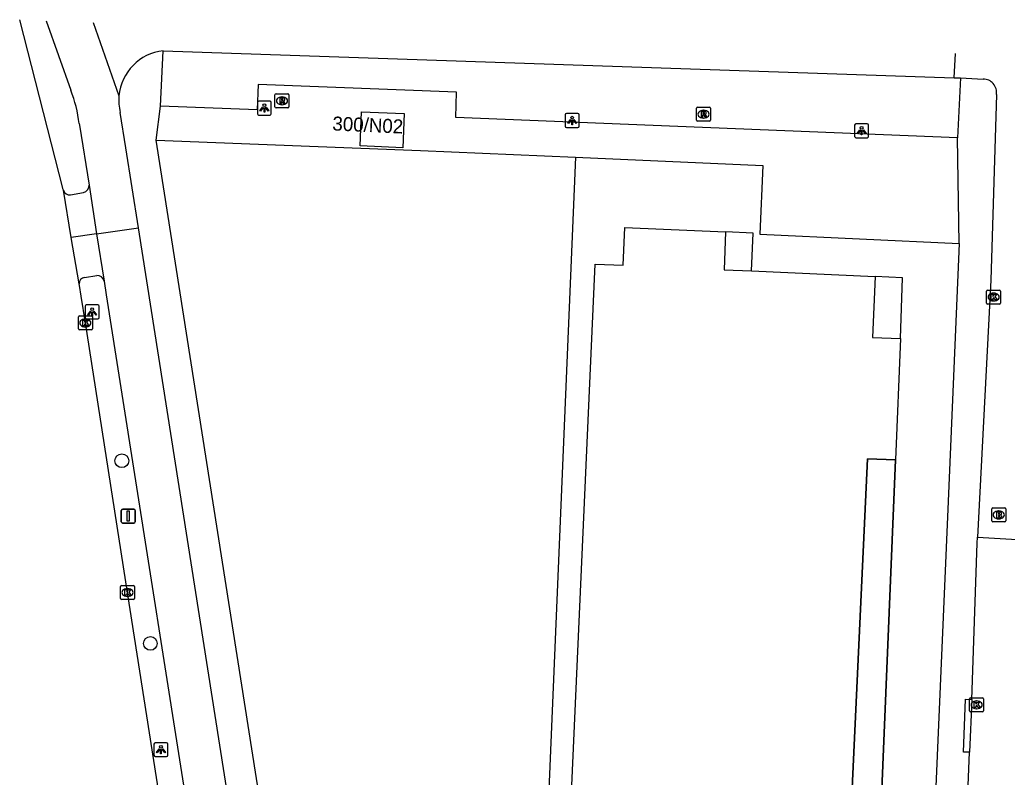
# Model space of a CAD drawing. Extents: x 160891 to 161384, y 386490 to 386907.
# Drawn here: x 160891.3 to 160961.8, y 386825.1 to 386879.2 of the extents above; entities that cross this region are included whole.
import ezdxf

# ---------------------------------------------------------------- set-up
doc = ezdxf.new("R2010")
doc.units = 0
for name, color, linetype in [('IMGEO_Boom', 7, 'Continuous'), ('IMGEO_Brandkraan', 7, 'Continuous'), ('IMGEO_Fietspad_gesloten', 7, 'Continuous'), ('IMGEO_Fietspad_open', 7, 'Continuous'), ('IMGEO_Kolk', 7, 'Continuous'), ('IMGEO_Lichtpunt', 7, 'Continuous'), ('IMGEO_Pand', 7, 'Continuous'), ('IMGEO_Pand_nummerreeks', 7, 'Continuous'), ('IMGEO_Pand_overbouw', 7, 'Continuous'), ('IMGEO_Rijbaan_lokaal_gesloten', 7, 'Continuous'), ('IMGEO_Rijbaan_lokaal_open', 7, 'Continuous'), ('IMGEO_Rioolput', 7, 'Continuous'), ('IMGEO_Verkeersbordpaal', 7, 'Continuous'), ('IMGEO_Voetpad_open', 7, 'Continuous')]:
    doc.layers.add(name, color=color, linetype=linetype)

msp = doc.modelspace()

# ---------------------------------------------------------------- linework, layer by layer
at = {"layer": 'IMGEO_Boom'}
for centre in [(160898.541, 386847.738), (160900.576, 386834.696)]:
    msp.add_circle(centre, 0.489, dxfattribs=at)
at = {"layer": 'IMGEO_Brandkraan'}
for p, q in [((160960.654, 386843.444), (160960.654, 386844.296)), ((160960.729, 386844.37), (160961.581, 386844.37)), ((160961.142, 386844.15), (160961.167, 386844.15)), ((160961.655, 386844.296), (160961.655, 386843.444)), ((160961.581, 386843.37), (160960.729, 386843.37)), ((160961.165, 386843.59), (160961.14, 386843.59))]:
    msp.add_line(p, q, dxfattribs=at)
for points in [[(160960.654, 386843.444), (160960.654, 386844.296)], [(160960.729, 386844.37), (160961.581, 386844.37)], [(160961.002, 386844.07), (160961.002, 386843.67), (160961.215, 386843.67)], [(160961.233, 386844.07), (160961.002, 386844.07)], [(160961.181, 386843.989), (160961.127, 386843.989), (160961.127, 386843.913)], [(160961.127, 386843.913), (160961.18, 386843.913)], [(160961.189, 386843.837), (160961.127, 386843.837), (160961.127, 386843.756)], [(160961.655, 386844.296), (160961.655, 386843.444)], [(160961.581, 386843.37), (160960.729, 386843.37)], [(160961.127, 386843.756), (160961.189, 386843.756)]]:
    msp.add_lwpolyline(points, dxfattribs=at)
for centre, radius, start, end in [((160960.731, 386844.294), 0.0765, 91.55205, 178.44795), ((160960.731, 386844.294), 0.0765, 91.55205, 178.44795), ((160961.182, 386843.951), 0.0379, 267.82845, 90.93552), ((160961.19, 386843.796), 0.0404, 269.87594, 90.50774), ((160961.237, 386843.925), 0.145, 59.4692, 91.53667), ((160961.262, 386843.972), 0.0922, 285.51372, 58.15012), ((160961.267, 386843.78), 0.105, 301.31148, 78.98903), ((160961.579, 386844.294), 0.0765, 1.55205, 88.44795), ((160961.579, 386844.294), 0.0765, 1.55205, 88.44795), ((160960.731, 386843.446), 0.0765, 181.55205, 268.44795), ((160960.731, 386843.446), 0.0765, 181.55205, 268.44795), ((160961.221, 386843.921), 0.251, 268.66757, 293.53466), ((160961.579, 386843.446), 0.0765, 271.55205, 358.44795), ((160961.579, 386843.446), 0.0765, 271.55205, 358.44795)]:
    msp.add_arc(centre, radius, start, end, dxfattribs=at)
for centre, major_axis, ratio, start_param, end_param in [((160961.141, 386843.87), (-0.387, 0.002), 0.722429, 4.712389, 7.853982), ((160961.166, 386843.87), (-0.39, 0.002), 0.717154, 1.570796, 4.712389)]:
    msp.add_ellipse(centre, major_axis=major_axis, ratio=ratio, start_param=start_param, end_param=end_param, dxfattribs=at)
at = {"layer": 'IMGEO_Fietspad_gesloten'}
for points in [[(160893.132, 386879.162), (160894.9, 386874.198)], [(160896.482, 386879.04), (160898.337, 386873.806)], [(160901.489, 386877.014), (160957.962, 386875.093)], [(160957.962, 386875.093), (160958.056, 386876.81)], [(160899.722, 386864.375), (160898.823, 386870.088), (160898.426, 386872.614)], [(160895.497, 386871.813), (160895.518, 386871.708), (160896.217, 386867.408)], [(160896.217, 386867.408), (160896.734, 386863.953)], [(160894.883, 386866.73), (160895.81, 386866.893)], [(160896.734, 386863.953), (160899.722, 386864.375)], [(160919.245, 386743.063), (160917.807, 386750), (160917.572, 386751.136), (160917.197, 386753.124), (160907.589, 386814.399), (160899.722, 386864.375)], [(160896.734, 386863.953), (160894.934, 386863.689)], [(160896.734, 386863.953), (160897.273, 386860.565)], [(160897.273, 386860.565), (160897.429, 386859.589), (160904.689, 386813.559), (160910.872, 386774.235), (160914.38, 386753.725), (160915.067, 386750), (160915.406, 386748.161), (160916.107, 386744.917), (160916.31, 386743.822)]]:
    msp.add_lwpolyline(points, dxfattribs=at)
for centre, radius, start, end in [((160901.888, 386873.47), 3.567, 96.42224, 174.58672), ((160885.253, 386870.516), 10.325, 7.21566, 20.89074), ((160901.872, 386873.471), 3.551, 174.5804, 193.95967), ((160894.793, 386867.155), 0.434, 193.70288, 281.96504), ((160895.601, 386867.477), 0.62, 289.71072, 353.65126)]:
    msp.add_arc(centre, radius, start, end, dxfattribs=at)
at = {"layer": 'IMGEO_Fietspad_open'}
for points in [[(160957.962, 386875.093), (160958.414, 386875.075)], [(160958.414, 386875.075), (160960.041, 386874.995)], [(160960.986, 386873.9), (160960.591, 386860.622), (160959.632, 386842.271)]]:
    msp.add_lwpolyline(points, dxfattribs=at)
msp.add_arc((160960.047, 386874.045), 0.95, 351.22726, 90.36203, dxfattribs=at)
at = {"layer": 'IMGEO_Kolk'}
for p, q in [((160960.287, 386859.002), (160960.287, 386859.854)), ((160960.362, 386859.928), (160961.214, 386859.928)), ((160960.775, 386859.708), (160960.8, 386859.708)), ((160961.288, 386859.854), (160961.288, 386859.002)), ((160961.214, 386858.928), (160960.362, 386858.928)), ((160960.798, 386859.148), (160960.773, 386859.148)), ((160895.436, 386857.151), (160895.436, 386858.003)), ((160895.511, 386858.077), (160896.363, 386858.077)), ((160896.437, 386858.003), (160896.437, 386857.151)), ((160895.947, 386857.297), (160895.922, 386857.297)), ((160895.924, 386857.857), (160895.949, 386857.857)), ((160896.363, 386857.077), (160895.511, 386857.077)), ((160898.443, 386837.906), (160898.443, 386838.758)), ((160898.518, 386838.832), (160899.37, 386838.832)), ((160898.931, 386838.612), (160898.956, 386838.612)), ((160899.444, 386838.758), (160899.444, 386837.906)), ((160899.37, 386837.832), (160898.518, 386837.832)), ((160898.954, 386838.052), (160898.929, 386838.052)), ((160959.074, 386829.883), (160959.074, 386830.735)), ((160959.149, 386830.809), (160960.001, 386830.809)), ((160959.562, 386830.589), (160959.587, 386830.589)), ((160960.075, 386830.735), (160960.075, 386829.883)), ((160960.001, 386829.809), (160959.149, 386829.809)), ((160959.585, 386830.029), (160959.56, 386830.029))]:
    msp.add_line(p, q, dxfattribs=at)
for points in [[(160960.287, 386859.002), (160960.287, 386859.854)], [(160960.362, 386859.928), (160961.214, 386859.928)], [(160960.608, 386859.628), (160960.731, 386859.628), (160960.731, 386859.477), (160960.861, 386859.628), (160961.025, 386859.628), (160960.879, 386859.477), (160961.032, 386859.228), (160960.88, 386859.228), (160960.795, 386859.392), (160960.731, 386859.325), (160960.731, 386859.228), (160960.608, 386859.228), (160960.608, 386859.628)], [(160961.288, 386859.854), (160961.288, 386859.002)], [(160961.214, 386858.928), (160960.362, 386858.928)], [(160895.436, 386857.151), (160895.436, 386858.003)], [(160895.511, 386858.077), (160896.363, 386858.077)], [(160896.437, 386858.003), (160896.437, 386857.151)], [(160895.757, 386857.777), (160895.88, 386857.777), (160895.88, 386857.626), (160896.01, 386857.777), (160896.174, 386857.777), (160896.028, 386857.626), (160896.181, 386857.377), (160896.029, 386857.377), (160895.944, 386857.541), (160895.88, 386857.474), (160895.88, 386857.377), (160895.757, 386857.377), (160895.757, 386857.777)], [(160896.363, 386857.077), (160895.511, 386857.077)], [(160898.443, 386837.906), (160898.443, 386838.758)], [(160898.518, 386838.832), (160899.37, 386838.832)], [(160898.764, 386838.532), (160898.887, 386838.532), (160898.887, 386838.381), (160899.017, 386838.532), (160899.181, 386838.532), (160899.035, 386838.381), (160899.188, 386838.132), (160899.036, 386838.132), (160898.951, 386838.296), (160898.887, 386838.229), (160898.887, 386838.132), (160898.764, 386838.132), (160898.764, 386838.532)], [(160899.444, 386838.758), (160899.444, 386837.906)], [(160899.37, 386837.832), (160898.518, 386837.832)], [(160959.074, 386829.883), (160959.074, 386830.735)], [(160959.149, 386830.809), (160960.001, 386830.809)], [(160959.395, 386830.509), (160959.518, 386830.509), (160959.518, 386830.358), (160959.648, 386830.509), (160959.812, 386830.509), (160959.666, 386830.358), (160959.819, 386830.109), (160959.667, 386830.109), (160959.582, 386830.273), (160959.518, 386830.206), (160959.518, 386830.109), (160959.395, 386830.109), (160959.395, 386830.509)], [(160960.075, 386830.735), (160960.075, 386829.883)], [(160960.001, 386829.809), (160959.149, 386829.809)]]:
    msp.add_lwpolyline(points, dxfattribs=at)
for centre, start, end in [((160960.364, 386859.852), 91.55205, 178.44795), ((160960.364, 386859.852), 91.55205, 178.44795), ((160961.212, 386859.852), 1.55205, 88.44795), ((160961.212, 386859.852), 1.55205, 88.44795), ((160960.364, 386859.004), 181.55205, 268.44795), ((160960.364, 386859.004), 181.55205, 268.44795), ((160961.212, 386859.004), 271.55205, 358.44795), ((160961.212, 386859.004), 271.55205, 358.44795), ((160895.513, 386858.001), 91.55205, 178.44795), ((160895.513, 386858.001), 91.55205, 178.44795), ((160896.361, 386858.001), 1.55205, 88.44795), ((160896.361, 386858.001), 1.55205, 88.44795), ((160895.513, 386857.153), 181.55205, 268.44795), ((160895.513, 386857.153), 181.55205, 268.44795), ((160896.361, 386857.153), 271.55205, 358.44795), ((160896.361, 386857.153), 271.55205, 358.44795), ((160898.52, 386838.756), 91.55205, 178.44795), ((160898.52, 386838.756), 91.55205, 178.44795), ((160899.368, 386838.756), 1.55205, 88.44795), ((160899.368, 386838.756), 1.55205, 88.44795), ((160898.52, 386837.908), 181.55205, 268.44795), ((160898.52, 386837.908), 181.55205, 268.44795), ((160899.368, 386837.908), 271.55205, 358.44795), ((160899.368, 386837.908), 271.55205, 358.44795), ((160959.151, 386830.733), 91.55205, 178.44795), ((160959.151, 386830.733), 91.55205, 178.44795), ((160959.999, 386830.733), 1.55205, 88.44795), ((160959.999, 386830.733), 1.55205, 88.44795), ((160959.151, 386829.885), 181.55205, 268.44795), ((160959.151, 386829.885), 181.55205, 268.44795), ((160959.999, 386829.885), 271.55205, 358.44795), ((160959.999, 386829.885), 271.55205, 358.44795)]:
    msp.add_arc(centre, 0.0765, start, end, dxfattribs=at)
for centre, major_axis, ratio, start_param, end_param in [((160960.774, 386859.428), (-0.387, 0.002), 0.722429, 4.712389, 7.853982), ((160960.799, 386859.428), (-0.39, 0.002), 0.717154, 1.570796, 4.712389), ((160895.923, 386857.577), (-0.387, 0.002), 0.722429, 4.712389, 7.853982), ((160895.948, 386857.577), (-0.39, 0.002), 0.717154, 1.570796, 4.712389), ((160898.93, 386838.332), (-0.387, 0.002), 0.722429, 4.712389, 7.853982), ((160898.955, 386838.332), (-0.39, 0.002), 0.717154, 1.570796, 4.712389), ((160959.561, 386830.309), (-0.387, 0.002), 0.722429, 4.712389, 7.853982), ((160959.586, 386830.309), (-0.39, 0.002), 0.717154, 1.570796, 4.712389)]:
    msp.add_ellipse(centre, major_axis=major_axis, ratio=ratio, start_param=start_param, end_param=end_param, dxfattribs=at)
at = {"layer": 'IMGEO_Lichtpunt'}
for p, q in [((160909.12, 386873.421), (160908.312, 386873.421)), ((160909.12, 386873.421), (160908.312, 386873.421)), ((160908.218, 386873.326), (160908.218, 386872.519)), ((160908.218, 386873.326), (160908.218, 386872.519)), ((160909.214, 386872.519), (160909.214, 386873.326)), ((160909.214, 386872.519), (160909.214, 386873.326)), ((160908.312, 386872.425), (160909.12, 386872.425)), ((160908.312, 386872.425), (160909.12, 386872.425)), ((160930.199, 386872.44), (160930.199, 386871.633)), ((160930.199, 386872.44), (160930.199, 386871.633)), ((160931.101, 386872.535), (160930.293, 386872.535)), ((160931.101, 386872.535), (160930.293, 386872.535)), ((160931.195, 386871.633), (160931.195, 386872.44)), ((160931.195, 386871.633), (160931.195, 386872.44)), ((160930.293, 386871.539), (160931.101, 386871.539)), ((160930.293, 386871.539), (160931.101, 386871.539)), ((160950.865, 386871.709), (160950.865, 386870.902)), ((160950.865, 386871.709), (160950.865, 386870.902)), ((160951.767, 386871.804), (160950.959, 386871.804)), ((160951.767, 386871.804), (160950.959, 386871.804)), ((160951.861, 386870.902), (160951.861, 386871.709)), ((160951.861, 386870.902), (160951.861, 386871.709)), ((160950.959, 386870.808), (160951.767, 386870.808)), ((160950.959, 386870.808), (160951.767, 386870.808)), ((160895.924, 386858.767), (160895.924, 386857.96)), ((160895.924, 386858.767), (160895.924, 386857.96)), ((160896.826, 386858.862), (160896.018, 386858.862)), ((160896.826, 386858.862), (160896.018, 386858.862)), ((160896.92, 386857.96), (160896.92, 386858.767)), ((160896.92, 386857.96), (160896.92, 386858.767)), ((160896.018, 386857.866), (160896.826, 386857.866)), ((160896.018, 386857.866), (160896.826, 386857.866)), ((160901.738, 386827.604), (160900.93, 386827.604)), ((160901.738, 386827.604), (160900.93, 386827.604)), ((160900.836, 386827.509), (160900.836, 386826.702)), ((160900.836, 386827.509), (160900.836, 386826.702)), ((160901.832, 386826.702), (160901.832, 386827.509)), ((160901.832, 386826.702), (160901.832, 386827.509)), ((160900.93, 386826.608), (160901.738, 386826.608)), ((160900.93, 386826.608), (160901.738, 386826.608))]:
    msp.add_line(p, q, dxfattribs=at)
for points in [[(160908.592, 386872.99), (160908.631, 386872.962), (160908.443, 386872.7), (160908.405, 386872.727), (160908.592, 386872.99)], [(160908.694, 386872.942), (160908.741, 386872.942), (160908.741, 386872.62), (160908.694, 386872.62), (160908.694, 386872.942)], [(160908.804, 386872.962), (160908.842, 386872.989), (160909.029, 386872.727), (160908.99, 386872.699), (160908.804, 386872.962)], [(160930.573, 386872.104), (160930.612, 386872.076), (160930.424, 386871.814), (160930.386, 386871.841), (160930.573, 386872.104)], [(160930.675, 386872.056), (160930.722, 386872.056), (160930.722, 386871.734), (160930.675, 386871.734), (160930.675, 386872.056)], [(160930.785, 386872.076), (160930.823, 386872.103), (160931.01, 386871.841), (160930.971, 386871.813), (160930.785, 386872.076)], [(160951.239, 386871.373), (160951.278, 386871.345), (160951.09, 386871.083), (160951.052, 386871.11), (160951.239, 386871.373)], [(160951.341, 386871.325), (160951.388, 386871.325), (160951.388, 386871.003), (160951.341, 386871.003), (160951.341, 386871.325)], [(160951.451, 386871.345), (160951.489, 386871.372), (160951.676, 386871.11), (160951.637, 386871.082), (160951.451, 386871.345)], [(160896.298, 386858.431), (160896.337, 386858.403), (160896.149, 386858.141), (160896.111, 386858.168), (160896.298, 386858.431)], [(160896.4, 386858.383), (160896.447, 386858.383), (160896.447, 386858.061), (160896.4, 386858.061), (160896.4, 386858.383)], [(160896.51, 386858.403), (160896.548, 386858.43), (160896.735, 386858.168), (160896.696, 386858.14), (160896.51, 386858.403)], [(160901.21, 386827.173), (160901.249, 386827.145), (160901.061, 386826.883), (160901.023, 386826.91), (160901.21, 386827.173)], [(160901.312, 386827.125), (160901.359, 386827.125), (160901.359, 386826.803), (160901.312, 386826.803), (160901.312, 386827.125)], [(160901.422, 386827.145), (160901.46, 386827.172), (160901.647, 386826.91), (160901.608, 386826.882), (160901.422, 386827.145)]]:
    msp.add_lwpolyline(points, dxfattribs=at)
for centre in [(160908.717, 386873.124), (160930.698, 386872.238), (160951.364, 386871.507), (160896.423, 386858.565), (160901.335, 386827.307)]:
    msp.add_circle(centre, 0.0994, dxfattribs=at)
for centre, start, end in [((160908.312, 386873.326), 90, 180), ((160908.312, 386873.326), 90, 180), ((160909.12, 386873.326), 0, 90), ((160909.12, 386873.326), 0, 90), ((160908.312, 386872.519), 180, 270), ((160908.312, 386872.519), 180, 270), ((160909.12, 386872.519), 270, 0), ((160909.12, 386872.519), 270, 360), ((160930.293, 386872.44), 90, 180), ((160930.293, 386872.44), 90, 180), ((160931.101, 386872.44), 0, 90), ((160931.101, 386872.44), 0, 90), ((160930.293, 386871.633), 180, 270), ((160930.293, 386871.633), 180, 270), ((160931.101, 386871.633), 270, 0), ((160931.101, 386871.633), 270, 360), ((160950.959, 386871.709), 90, 180), ((160950.959, 386871.709), 90, 180), ((160951.767, 386871.709), 0, 90), ((160951.767, 386871.709), 0, 90), ((160950.959, 386870.902), 180, 270), ((160950.959, 386870.902), 180, 270), ((160951.767, 386870.902), 270, 0), ((160951.767, 386870.902), 270, 360), ((160896.018, 386858.767), 90, 180), ((160896.018, 386858.767), 90, 180), ((160896.826, 386858.767), 0, 90), ((160896.826, 386858.767), 0, 90), ((160896.018, 386857.96), 180, 270), ((160896.018, 386857.96), 180, 270), ((160896.826, 386857.96), 270, 0), ((160896.826, 386857.96), 270, 360), ((160900.93, 386827.509), 90, 180), ((160900.93, 386827.509), 90, 180), ((160901.738, 386827.509), 0, 90), ((160901.738, 386827.509), 0, 90), ((160900.93, 386826.702), 180, 270), ((160900.93, 386826.702), 180, 270), ((160901.738, 386826.702), 270, 0), ((160901.738, 386826.702), 270, 360)]:
    msp.add_arc(centre, 0.0946, start, end, dxfattribs=at)
at = {"layer": 'IMGEO_Pand'}
for points in [[(160918.609, 386870.095), (160915.56, 386870.217), (160915.658, 386872.659), (160918.707, 386872.537), (160918.609, 386870.095)], [(160929.668, 386802.21), (160932.347, 386861.777), (160934.345, 386861.699), (160934.451, 386864.398), (160941.654, 386864.075), (160941.548, 386861.376), (160943.509, 386861.288), (160952.319, 386860.893), (160952.148, 386856.549), (160954.129, 386856.46), (160953.788, 386847.794)], [(160952.108, 386763.787), (160950.315, 386763.859), (160951.446, 386797.676), (160949.448, 386797.758), (160951.78, 386847.873), (160953.788, 386847.794)]]:
    msp.add_lwpolyline(points, dxfattribs=at)
at = {"layer": 'IMGEO_Pand_overbouw'}
for points in [[(160941.654, 386864.075), (160941.548, 386861.376), (160943.509, 386861.288), (160943.619, 386863.992)], [(160954.129, 386856.46), (160954.283, 386860.798), (160952.319, 386860.893), (160952.148, 386856.549)], [(160953.788, 386847.794), (160951.78, 386847.873), (160949.448, 386797.758), (160951.446, 386797.676), (160950.315, 386763.859), (160952.108, 386763.787), (160953.498, 386797.543), (160953.65, 386801.238), (160953.658, 386801.438), (160953.82, 386805.388), (160953.828, 386805.588), (160952.045, 386805.661), (160952.198, 386809.36)]]:
    msp.add_lwpolyline(points, close=True, dxfattribs=at)
at = {"layer": 'IMGEO_Rijbaan_lokaal_gesloten'}
for points in [[(160894.371, 386867.052), (160894.361, 386867.114), (160891.251, 386879.23)], [(160894.934, 386863.689), (160894.371, 386867.052)], [(160895.489, 386860.369), (160894.934, 386863.689)], [(160913.758, 386743.775), (160912.804, 386750), (160912.737, 386750.44), (160909.252, 386772.655), (160906.087, 386792.878), (160902.899, 386813.113), (160898.944, 386838.332), (160895.937, 386857.577), (160895.636, 386859.48), (160895.508, 386860.258), (160895.489, 386860.369)]]:
    msp.add_lwpolyline(points, dxfattribs=at)
at = {"layer": 'IMGEO_Rijbaan_lokaal_open'}
for points in [[(160959.238, 386830.691), (160959.61, 386841.85), (160959.632, 386842.271)], [(160959.632, 386842.271), (160962.072, 386842.148), (160963.58, 386842.073)], [(160959.238, 386830.691), (160959.074, 386826.917)], [(160958.543, 386813.81), (160959.074, 386826.917)]]:
    msp.add_lwpolyline(points, dxfattribs=at)
at = {"layer": 'IMGEO_Rioolput'}
for p, q in [((160909.474, 386873.012), (160909.474, 386873.864)), ((160909.549, 386873.938), (160910.401, 386873.938)), ((160909.962, 386873.718), (160909.987, 386873.718)), ((160910.475, 386873.864), (160910.475, 386873.012)), ((160910.401, 386872.938), (160909.549, 386872.938)), ((160909.985, 386873.158), (160909.96, 386873.158)), ((160939.576, 386872.061), (160939.576, 386872.913)), ((160939.651, 386872.987), (160940.503, 386872.987)), ((160940.064, 386872.767), (160940.089, 386872.767)), ((160940.577, 386872.913), (160940.577, 386872.061)), ((160940.503, 386871.987), (160939.651, 386871.987)), ((160940.087, 386872.207), (160940.062, 386872.207))]:
    msp.add_line(p, q, dxfattribs=at)
for points in [[(160909.474, 386873.012), (160909.474, 386873.864)], [(160909.549, 386873.938), (160910.401, 386873.938)], [(160910.063, 386873.636), (160909.811, 386873.638), (160909.811, 386873.238)], [(160909.811, 386873.238), (160909.935, 386873.238), (160909.935, 386873.4), (160909.946, 386873.4)], [(160909.989, 386873.557), (160909.935, 386873.557), (160909.935, 386873.476)], [(160909.935, 386873.476), (160909.987, 386873.476)], [(160910.475, 386873.864), (160910.475, 386873.012)], [(160910.401, 386872.938), (160909.549, 386872.938)], [(160909.993, 386873.371), (160910.064, 386873.238), (160910.204, 386873.238), (160910.139, 386873.364)], [(160939.576, 386872.061), (160939.576, 386872.913)], [(160939.651, 386872.987), (160940.503, 386872.987)], [(160940.165, 386872.685), (160939.913, 386872.687), (160939.913, 386872.287)], [(160940.577, 386872.913), (160940.577, 386872.061)], [(160940.503, 386871.987), (160939.651, 386871.987)], [(160939.913, 386872.287), (160940.037, 386872.287), (160940.037, 386872.449), (160940.048, 386872.449)], [(160940.091, 386872.606), (160940.037, 386872.606), (160940.037, 386872.525)], [(160940.037, 386872.525), (160940.089, 386872.525)], [(160940.095, 386872.42), (160940.166, 386872.287), (160940.306, 386872.287), (160940.241, 386872.413)]]:
    msp.add_lwpolyline(points, dxfattribs=at)
for centre, radius, start, end in [((160909.551, 386873.862), 0.0765, 91.55205, 178.44795), ((160909.551, 386873.862), 0.0765, 91.55205, 178.44795), ((160909.945, 386873.347), 0.0533, 26.02933, 88.69889), ((160909.971, 386873.665), 0.19, 274.7715, 282.96867), ((160909.995, 386873.461), 0.0964, 77.00612, 93.18647), ((160910.009, 386873.518), 0.0378, 276.66336, 79.67722), ((160910.062, 386873.526), 0.109, 350.36119, 89.41601), ((160910.06, 386873.526), 0.112, 277.58423, 350.98172), ((160910.044, 386873.311), 0.108, 29.51342, 73.79051), ((160910.399, 386873.862), 0.0765, 1.55205, 88.44795), ((160910.399, 386873.862), 0.0765, 1.55205, 88.44795), ((160909.551, 386873.014), 0.0765, 181.55205, 268.44795), ((160909.551, 386873.014), 0.0765, 181.55205, 268.44795), ((160910.399, 386873.014), 0.0765, 271.55205, 358.44795), ((160910.399, 386873.014), 0.0765, 271.55205, 358.44795), ((160939.653, 386872.911), 0.0765, 91.55205, 178.44795), ((160939.653, 386872.911), 0.0765, 91.55205, 178.44795), ((160940.164, 386872.575), 0.109, 350.36119, 89.41601), ((160940.501, 386872.911), 0.0765, 1.55205, 88.44795), ((160940.501, 386872.911), 0.0765, 1.55205, 88.44795), ((160939.653, 386872.063), 0.0765, 181.55205, 268.44795), ((160939.653, 386872.063), 0.0765, 181.55205, 268.44795), ((160940.047, 386872.396), 0.0533, 26.02933, 88.69889), ((160940.073, 386872.714), 0.19, 274.7715, 282.96867), ((160940.097, 386872.51), 0.0964, 77.00612, 93.18647), ((160940.111, 386872.567), 0.0378, 276.66336, 79.67722), ((160940.162, 386872.575), 0.112, 277.58423, 350.98172), ((160940.146, 386872.36), 0.108, 29.51342, 73.79051), ((160940.501, 386872.063), 0.0765, 271.55205, 358.44795), ((160940.501, 386872.063), 0.0765, 271.55205, 358.44795)]:
    msp.add_arc(centre, radius, start, end, dxfattribs=at)
for centre, major_axis, ratio, start_param, end_param in [((160909.961, 386873.438), (-0.387, 0.002), 0.722429, 4.712389, 7.853982), ((160909.986, 386873.438), (-0.39, 0.002), 0.717154, 1.570796, 4.712389), ((160940.063, 386872.487), (-0.387, 0.002), 0.722429, 4.712389, 7.853982), ((160940.088, 386872.487), (-0.39, 0.002), 0.717154, 1.570796, 4.712389)]:
    msp.add_ellipse(centre, major_axis=major_axis, ratio=ratio, start_param=start_param, end_param=end_param, dxfattribs=at)
at = {"layer": 'IMGEO_Verkeersbordpaal'}
for p, q in [((160898.502, 386843.387), (160898.502, 386844.187)), ((160898.502, 386844.187), (160898.502, 386843.387)), ((160898.602, 386844.287), (160899.392, 386844.287)), ((160899.392, 386844.287), (160898.602, 386844.287)), ((160899.492, 386844.187), (160899.492, 386843.387)), ((160899.492, 386843.387), (160899.492, 386844.187)), ((160899.392, 386843.287), (160898.602, 386843.287)), ((160898.602, 386843.287), (160899.392, 386843.287))]:
    msp.add_line(p, q, dxfattribs=at)
msp.add_lwpolyline([(160898.922, 386844.162), (160899.072, 386844.162), (160899.072, 386843.412), (160898.922, 386843.412), (160898.922, 386844.162)], dxfattribs=at)
for centre, start, end in [((160898.602, 386844.187), 90, 180), ((160898.602, 386844.187), 90, 180), ((160899.392, 386844.187), 0, 90), ((160899.392, 386844.187), 360, 90), ((160898.602, 386843.387), 180, 270), ((160898.602, 386843.387), 180, 270), ((160899.392, 386843.387), 270, 0), ((160899.392, 386843.387), 270, 0)]:
    msp.add_arc(centre, 0.1, start, end, dxfattribs=at)
at = {"layer": 'IMGEO_Voetpad_open'}
for points in [[(160901.306, 386873.07), (160901.489, 386877.014)], [(160958.414, 386875.075), (160958.216, 386870.789)], [(160958.216, 386870.789), (160922.377, 386872.253), (160922.446, 386874.058), (160908.279, 386874.602), (160908.206, 386872.785), (160901.306, 386873.07)], [(160901.002, 386870.642), (160901.306, 386873.07)], [(160901.002, 386870.642), (160919.86, 386869.902), (160930.929, 386869.413)], [(160920.871, 386743.948), (160919.923, 386750), (160909.808, 386814.589), (160901.002, 386870.642)], [(160958.321, 386863.241), (160958.216, 386870.789)], [(160930.929, 386869.413), (160927.927, 386798.235), (160929.5, 386798.18)], [(160930.929, 386869.413), (160944.3, 386868.823), (160944.088, 386863.91), (160958.321, 386863.241)], [(160958.321, 386863.241), (160957.528, 386844.274), (160956.638, 386823.929), (160956.62, 386823.496)], [(160895.883, 386860.825), (160896.751, 386860.973)], [(160953.788, 386847.794), (160952.198, 386809.36), (160955.314, 386809.236), (160954.852, 386797.5), (160953.498, 386797.543), (160952.108, 386763.787)], [(160959.074, 386826.917), (160958.637, 386826.939), (160958.774, 386830.722), (160959.238, 386830.691)]]:
    msp.add_lwpolyline(points, dxfattribs=at)
for centre, radius, start, end in [((160895.931, 386860.385), 0.442, 96.23838, 182.10529), ((160896.786, 386860.48), 0.494, 9.92501, 94.05197)]:
    msp.add_arc(centre, radius, start, end, dxfattribs=at)

# ---------------------------------------------------------------- texts
at = {"layer": 'IMGEO_Pand_nummerreeks'}
msp.add_text('300/N02', height=1, rotation=357.42308, dxfattribs=at).set_placement((160913.558, 386871.328))

doc.saveas('drawing.dxf')
